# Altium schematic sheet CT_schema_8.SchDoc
size 254 x 194 mm
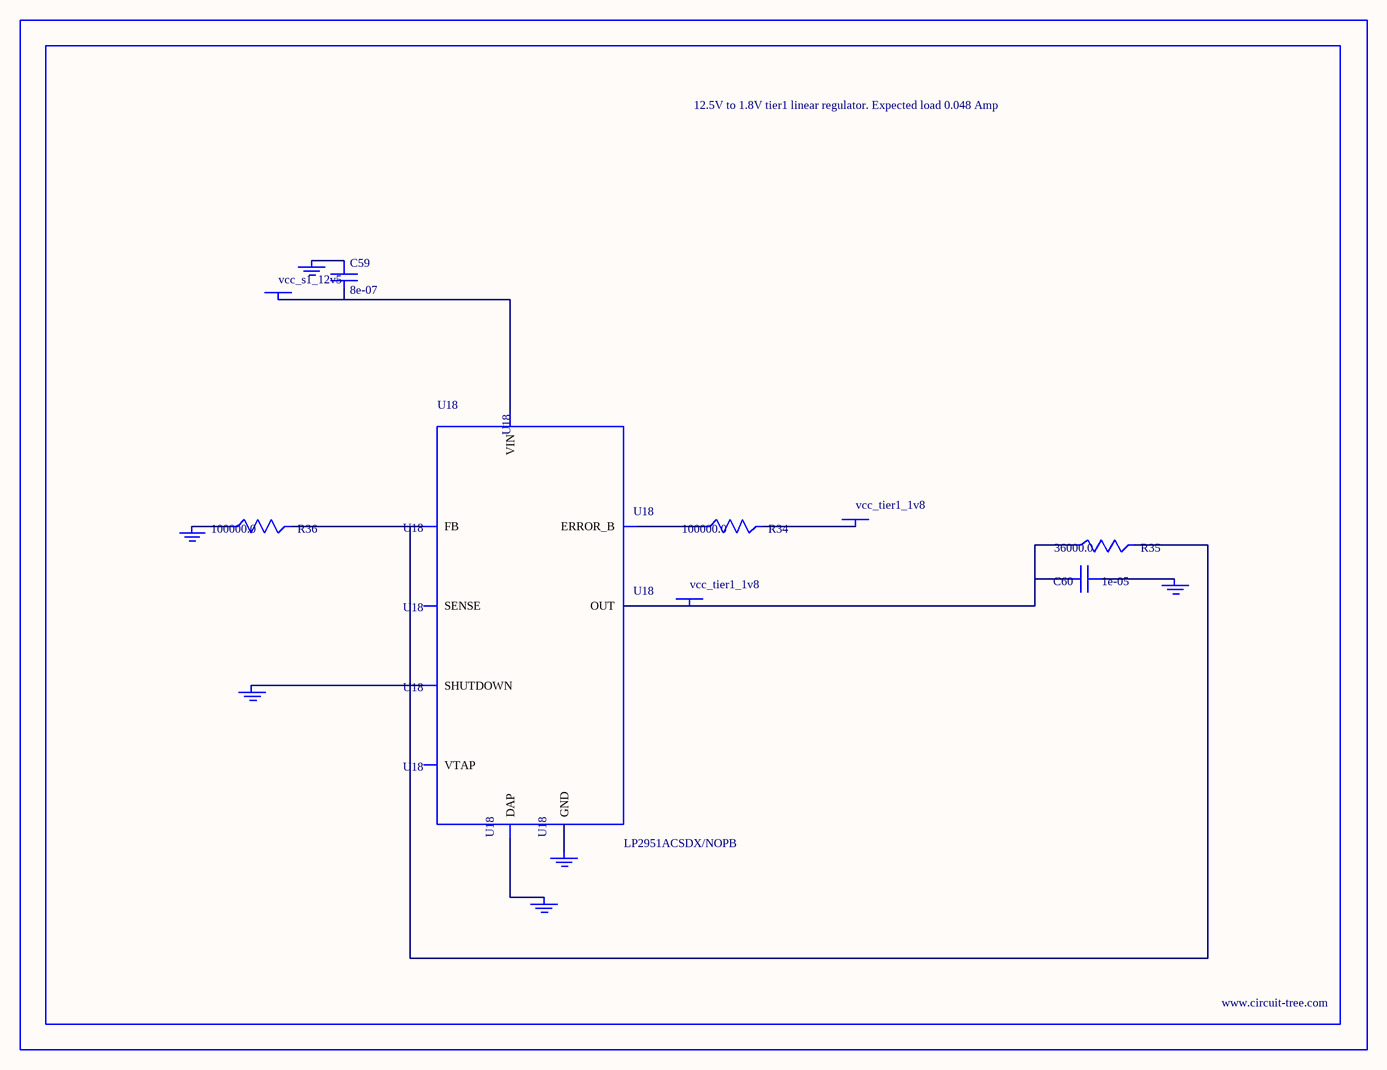
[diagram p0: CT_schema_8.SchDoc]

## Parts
BORDER7  (no value)
C59  8e-07  [R0603]
C60  1e-05  [C0805]
GND_INSTANCE_7_0  (no value)
GND_INSTANCE_7_1  (no value)
GND_INSTANCE_7_2  (no value)
GND_INSTANCE_7_3  (no value)
GND_INSTANCE_7_4  (no value)
GND_INSTANCE_7_5  (no value)
POWER_INSTANCE_7_0  vcc_tier1_1v8
POWER_INSTANCE_7_1  vcc_s1_12v5
POWER_INSTANCE_7_2  vcc_tier1_1v8
R34  100000.0  [R0603]
R35  36000.0  [R0603]
R36  100000.0  [R0603]
U18  LP2951ACSDX/NOPB  [WSON-8]

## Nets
NetC59_1: C59.1 GND_INSTANCE_7_3.0(GND)
NetC59_2: C59.2 POWER_INSTANCE_7_1.0(PWR) U18.8(VIN)
NetC60_1: C60.1 GND_INSTANCE_7_0.0(GND)
NetC60_2: C60.2 POWER_INSTANCE_7_2.0(PWR) R35.1 U18.1(OUT)
NetGND_INSTANCE_7_1_0: GND_INSTANCE_7_1.0(GND) U18.3(SHUTDOWN)
NetGND_INSTANCE_7_2_0: GND_INSTANCE_7_2.0(GND) R36.1
NetGND_INSTANCE_7_4_0: GND_INSTANCE_7_4.0(GND) U18.PAD(DAP)
NetGND_INSTANCE_7_5_0: GND_INSTANCE_7_5.0(GND) U18.4(GND)
NetPOWER_INSTANCE_7_0_0: POWER_INSTANCE_7_0.0(PWR) R34.2
NetR34_1: R34.1 U18.5(ERROR_B)
NetR35_2: R35.2 R36.2 U18.7(FB)

Not connected (* = marked no-connect by the designer): U18 2(SENSE) 6(VTAP)

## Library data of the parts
BORDER7 = BORDER_PAGE7
C59 = C59
C60 = GRM219R60J106ME19D
GND_INSTANCE_7_0-GND_INSTANCE_7_5 = GND
POWER_INSTANCE_7_0-POWER_INSTANCE_7_2 = PWR
R34 R36 = RC0603JR-07100KL
R35 = RC0603JR-0736KL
